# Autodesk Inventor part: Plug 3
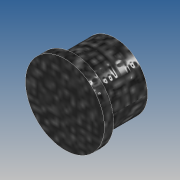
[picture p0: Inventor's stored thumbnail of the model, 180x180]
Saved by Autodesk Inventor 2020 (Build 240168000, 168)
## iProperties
Created: 2019-10
Part Number: Plug 3
Material: Generic
Document SubType Name: Modeling
Designer: yello
Density: 1 g/cm^3
Appearance: Default
Author: yello
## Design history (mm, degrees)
sketch "Sketch1"
  geometry: C1 r 4.25 at (0, 0); 1 further point
  constraints: 1 centre point, 1 coincident
  dimensions: "d0" = 8.5 diameter of C1
extrude "Extrusion1" new body sketch "Sketch1" distance "d1" = 1; taper "d2" = 0 deg
sketch "Sketch2"
  geometry: C1 r 3.5 at (0, 0); 1 further point
  constraints: 1 centre point, 1 coincident
  dimensions: "d3" = 7 diameter of C1
extrude "Extrusion2" join sketch "Sketch2" distance "d4" = 4.4; taper "d5" = 0 deg
body "Solid1"
